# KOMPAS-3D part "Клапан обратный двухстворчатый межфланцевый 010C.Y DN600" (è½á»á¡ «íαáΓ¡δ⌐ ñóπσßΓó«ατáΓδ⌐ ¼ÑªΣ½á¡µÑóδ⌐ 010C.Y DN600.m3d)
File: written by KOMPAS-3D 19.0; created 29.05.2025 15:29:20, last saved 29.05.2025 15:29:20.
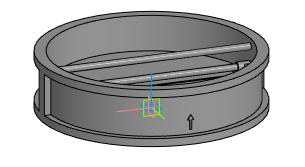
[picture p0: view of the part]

Document properties: Полное имя файла: E:\Dendor Работа Сачек\3D для проекитирвщиков\5.2 Тип 010C, 010C.Y Клапан обратный двухстворчатый межфланцевый\stp_Клапан обратный двухстворчатый межфланцевый 010C.Y\Клапан обратный двухстворчатый межфланцевый 010C.Y DN600.m3d

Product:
- Part/product: Клапан обратный двухстворчатый межфланцевый 010C.Y DN600

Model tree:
1. Операция без истории:1  (labels: Клапан обратный двухстворчатый межфланцевый 010C.Y DN600)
